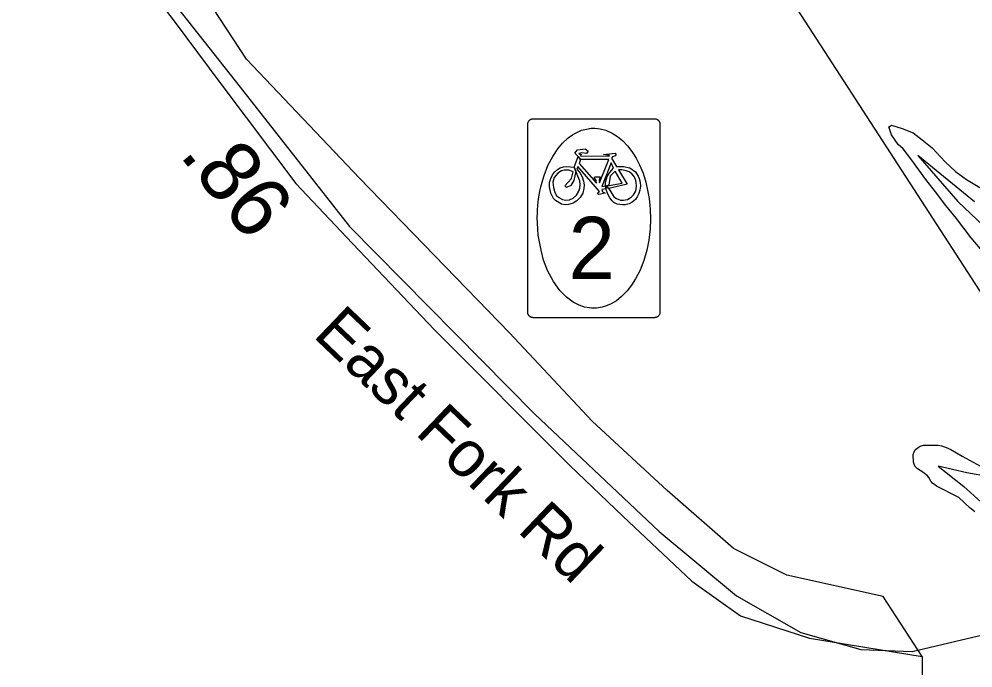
# Model space of a CAD drawing. Extents: x 1662474 to 1856135, y 779280 to 917889.
# Drawn here: x 1719329 to 1721283, y 823551 to 824881 of the extents above; entities that cross this region are included whole.
import ezdxf

# ---------------------------------------------------------------- set-up
doc = ezdxf.new("R2010")
doc.units = 0
for name, color, linetype in [('Exist Boundary Political City Limit New', 7, 'Continuous'), ('Exist Boundary Political City Limit New Hole', 7, 'Continuous'), ('Exist Hydrographic Lake Shore', 7, 'Continuous'), ('Exist Road Primary NC Shield Bike CELL', 7, 'Continuous'), ('Exist Road Primary NC Shield Bike NC Label', 7, 'Continuous'), ('Exist Road Secondary Mileage Tenths English Label', 7, 'Continuous'), ('Exist Road Secondary Structure Standard Bridge Number Label', 7, 'Continuous'), ('Exist Road Secondary Type 51 Attributed', 7, 'Continuous'), ('Exist Road Secondary Type 51 Label', 7, 'Continuous'), ('Map Preparation Boundary City Limit Buffer Line', 7, 'Continuous'), ('Old_Level_44', 7, 'Continuous')]:
    doc.layers.add(name, color=color, linetype=linetype)

msp = doc.modelspace()

# ---------------------------------------------------------------- linework, layer by layer
at = {"layer": 'Exist Boundary Political City Limit New'}
for points in [[(1719315.9, 825244.6), (1719397.1, 825175.9), (1719546.9, 825009.6), (1719554, 825000), (1719602.4, 824935.2), (1719646.4, 824876.2), (1719742.4, 824747.6), (1719896.1, 824543.8), (1720000, 824433.9), (1720179, 824244.4), (1720457.6, 823965.8), (1720565.8, 823861.8), (1720707.1, 823728.7), (1720806.9, 823658), (1720948.4, 823612.2), (1721179.4, 823574.5)], [(1721179.4, 823574.5), (1721179.4, 823520.1)]]:
    msp.add_lwpolyline(points, dxfattribs=at)
at = {"layer": 'Exist Boundary Political City Limit New Hole'}
for points in [[(1721179.4, 823574.5), (1721099.2, 823697.6), (1720902.1, 823741.4), (1720792.6, 823796.1), (1720656.5, 823914.4), (1720503.1, 824056.8), (1720333.4, 824237.4), (1720026.6, 824554.9), (1719795, 824798.7), (1719645.5, 825027.3), (1719572.1, 825148.3), (1719468, 825252.3), (1719304.1, 825346.5)], [(1719315.9, 825244.6), (1719397.1, 825175.9), (1719546.9, 825009.6), (1719554, 825000), (1719602.4, 824935.2), (1719646.4, 824876.2), (1719742.4, 824747.6), (1719896.1, 824543.8), (1720000, 824433.9), (1720179, 824244.4), (1720457.6, 823965.8), (1720565.8, 823861.8), (1720707.1, 823728.7), (1720806.9, 823658), (1720948.4, 823612.2), (1721179.4, 823574.5)]]:
    msp.add_lwpolyline(points, dxfattribs=at)
at = {"layer": 'Exist Hydrographic Lake Shore'}
for points in [[(1721298.5, 824409.5), (1721279.4, 824432.3), (1721249.5, 824472.2), (1721227.4, 824498.7), (1721206.6, 824526.8), (1721186.8, 824552), (1721158.1, 824591.6), (1721140, 824614.4), (1721130.2, 824623.9), (1721116.4, 824643.1), (1721111.1, 824659.9), (1721114, 824661.7), (1721116.4, 824663), (1721138.4, 824656.4), (1721160.5, 824647.2), (1721179.4, 824633.1), (1721199.6, 824616.6), (1721226.1, 824588.2), (1721247.4, 824568.5), (1721269.9, 824551.8), (1721297.2, 824535.8)], [(1721286.8, 823870.9), (1721277, 823879.1), (1721254.4, 823900.6), (1721208.5, 823923.7), (1721204.9, 823926), (1721200.6, 823929.4), (1721197.2, 823933.6), (1721193, 823941.5), (1721190.1, 823944.9), (1721180.6, 823952), (1721169.6, 823959.1), (1721164.4, 823964.6), (1721162.6, 823968.8), (1721161.5, 823973), (1721161, 823988.2), (1721162.9, 823994.2), (1721165.8, 823998.4), (1721171, 824002.9), (1721174.9, 824005.3), (1721182, 824007.4), (1721212.1, 824007.9), (1721219, 824006.3), (1721226.9, 824003.7), (1721237.6, 823999), (1721260.8, 823985.3), (1721306.4, 823960.7)]]:
    msp.add_lwpolyline(points, dxfattribs=at)
at = {"layer": 'Exist Road Primary NC Shield Bike CELL'}
for points in [[(1720381, 824676.2), (1720381.8, 824676.3), (1720414.8, 824676.3), (1720598.2, 824676.3), (1720631.2, 824676.3), (1720632.4, 824676.2), (1720633, 824676.1), (1720633.8, 824675.9), (1720634.5, 824675.7), (1720635.2, 824675.5), (1720636.5, 824674.8), (1720637.2, 824674.4), (1720637.8, 824674), (1720638.5, 824673.3), (1720639.4, 824672.3), (1720640.1, 824671.5), (1720640.3, 824671.1), (1720640.5, 824670.7), (1720640.8, 824670.2), (1720641, 824669.8), (1720641.2, 824669.3), (1720641.5, 824668.6), (1720641.7, 824667.6), (1720641.8, 824666.8), (1720641.9, 824666.4), (1720641.9, 824666), (1720641.9, 824632.5), (1720641.9, 824312.7), (1720641.9, 824279.6), (1720641.8, 824278.4), (1720641.7, 824277.8), (1720641.6, 824277), (1720641.4, 824276.3), (1720641.1, 824275.6), (1720640.4, 824274.2), (1720640.1, 824273.6), (1720639.6, 824273), (1720639, 824272.3), (1720638.5, 824271.9), (1720638, 824271.3), (1720637.7, 824271.1), (1720637.2, 824270.7), (1720636.8, 824270.4), (1720636.4, 824270.2), (1720635.9, 824270), (1720635, 824269.6), (1720634.2, 824269.3), (1720633.3, 824269.1), (1720632.9, 824269), (1720632.4, 824268.9), (1720632.1, 824268.9), (1720631.7, 824268.9), (1720631.1, 824268.8), (1720598.1, 824268.8), (1720414.8, 824268.8), (1720381.8, 824268.8), (1720381.2, 824268.9), (1720380.6, 824268.9), (1720380, 824269), (1720379.2, 824269.2), (1720378.5, 824269.4), (1720377.8, 824269.7), (1720377.1, 824270), (1720376.5, 824270.3), (1720375.9, 824270.7), (1720375.2, 824271.1), (1720374.9, 824271.4), (1720374.5, 824271.8), (1720374.3, 824272), (1720373.9, 824272.5), (1720373.5, 824272.9), (1720373.1, 824273.4), (1720372.8, 824273.8), (1720372.6, 824274.2), (1720372.3, 824274.8), (1720372, 824275.3), (1720371.8, 824275.8), (1720371.7, 824276.1), (1720371.6, 824276.4), (1720371.5, 824276.7), (1720371.5, 824276.9), (1720371.4, 824277.1), (1720371.3, 824277.3), (1720371.3, 824277.6), (1720371.2, 824277.8), (1720371.2, 824278.1), (1720371.2, 824278.3), (1720371.2, 824278.5), (1720371.1, 824278.8), (1720371.1, 824279.4), (1720371.1, 824312.6), (1720371.1, 824632.5), (1720371.1, 824665.6), (1720371.2, 824666.7), (1720371.3, 824667.4), (1720371.4, 824668.1), (1720371.6, 824668.9), (1720371.9, 824669.6), (1720372.6, 824670.9), (1720373, 824671.5), (1720373.4, 824672.1), (1720374, 824672.8), (1720375, 824673.8), (1720375.8, 824674.4), (1720376.3, 824674.7), (1720376.6, 824674.9), (1720377.1, 824675.2), (1720377.6, 824675.3), (1720378, 824675.6), (1720378.8, 824675.8), (1720379.7, 824676), (1720380.6, 824676.2)], [(1720506.5, 824288.3), (1720501.8, 824288.5), (1720497.4, 824288.9), (1720487.5, 824290.6), (1720476.2, 824294.7), (1720469.7, 824297.9), (1720464.4, 824300.9), (1720458.7, 824304.8), (1720450.7, 824310.7), (1720437, 824324.6), (1720423.5, 824342.6), (1720411.7, 824365.7), (1720403.4, 824386.6), (1720398.2, 824407), (1720392.5, 824437.9), (1720390.7, 824462.3), (1720390.6, 824474.2), (1720390.7, 824482.8), (1720391, 824489), (1720391.7, 824498.3), (1720393.1, 824512.6), (1720395.8, 824527.3), (1720397.8, 824536.7), (1720399.1, 824541.9), (1720401.8, 824551.5), (1720404.4, 824560), (1720412.3, 824580.5), (1720422.1, 824599.1), (1720432.9, 824614.7), (1720442.4, 824626.4), (1720453.9, 824637.2), (1720462.8, 824643.2), (1720467.4, 824645.9), (1720472.7, 824648.7), (1720481.3, 824652.7), (1720491.6, 824655.3), (1720501, 824656.8), (1720508.7, 824657), (1720519.5, 824655.8), (1720530.9, 824652.8), (1720543.9, 824647.1), (1720555.2, 824640.2), (1720564.9, 824631.9), (1720575.6, 824620.9), (1720584.3, 824609.5), (1720592.9, 824595.6), (1720600, 824582), (1720607.2, 824564.8), (1720612.7, 824546.7), (1720616.7, 824529.7), (1720619.7, 824513.1), (1720621.2, 824498.5), (1720621.8, 824490.4), (1720622.7, 824471.4), (1720621.8, 824451.1), (1720619.1, 824427.5), (1720614.8, 824406.8), (1720609, 824385.9), (1720601.2, 824365.8), (1720592.1, 824348.2), (1720583.5, 824335.1), (1720574.7, 824323.6), (1720563.4, 824311.9), (1720553.1, 824303.6), (1720541.9, 824297.1), (1720530.4, 824292.2), (1720523.3, 824290.3), (1720519.2, 824289.6), (1720515.7, 824288.9), (1720511.9, 824288.6)], [(1720526, 824603), (1720550.1, 824605.9), (1720551.9, 824604.1), (1720550.4, 824600.3), (1720544.5, 824598.5), (1720542.9, 824595.3), (1720553, 824578.2), (1720567.5, 824578.8), (1720580.4, 824576), (1720591.6, 824567.4), (1720597, 824558.8), (1720599.5, 824554.2), (1720601.4, 824546.4), (1720601.8, 824538.2), (1720600.7, 824529.7), (1720598.9, 824523.2), (1720595.3, 824516.3), (1720591.8, 824511.2), (1720585, 824505.7), (1720578.9, 824502.2), (1720570.5, 824500.1), (1720565.2, 824499.8), (1720554.5, 824501.5), (1720547.6, 824505), (1720544.2, 824507.9), (1720539, 824514.3), (1720535.7, 824520.4), (1720531, 824532.6), (1720530, 824538.5), (1720537.4, 824533.2), (1720543.2, 824523.3), (1720547.3, 824516.6), (1720552.6, 824512.8), (1720560.8, 824509.5), (1720566.9, 824509.3), (1720575.1, 824511.2), (1720582.6, 824515.4), (1720588, 824520.8), (1720592.3, 824527.9), (1720593.7, 824537.9), (1720593.5, 824546.1), (1720591.6, 824552.8), (1720588.1, 824558.9), (1720584.5, 824563.2), (1720578.6, 824567.7), (1720572.9, 824569.5), (1720563.5, 824571.4), (1720557, 824572), (1720574.5, 824542.5), (1720537.4, 824533.2), (1720530, 824538.5), (1720564.2, 824544.7), (1720549.9, 824569.1), (1720540.1, 824558.5), (1720537.2, 824540), (1720530, 824538.5), (1720530.4, 824546.3), (1720533.5, 824558.1), (1720538.9, 824566.3), (1720546.7, 824575.2), (1720541.8, 824585.7), (1720523, 824537.8), (1720530.1, 824538.6), (1720531, 824532.6), (1720522.6, 824531.6), (1720524.4, 824526.5), (1720529.4, 824523.7), (1720516.9, 824520.9), (1720513.8, 824524.8), (1720518.3, 824527.2), (1720473.6, 824578.3), (1720471.9, 824573.4), (1720478.1, 824565.1), (1720482.3, 824557.1), (1720485, 824548.5), (1720486.4, 824541.1), (1720485.7, 824533.6), (1720483.6, 824523.7), (1720478.7, 824514.8), (1720471.8, 824508.1), (1720464, 824503.3), (1720454.4, 824500.9), (1720447.4, 824500.3), (1720440.3, 824501.2), (1720428, 824508.8), (1720424, 824513.3), (1720418.3, 824523.7), (1720415.8, 824536.6), (1720415.7, 824545.8), (1720418, 824554), (1720421.6, 824561.3), (1720425.8, 824566.6), (1720431.9, 824572.6), (1720437.2, 824576), (1720444.1, 824578), (1720451.1, 824578.7), (1720466.3, 824577), (1720469.8, 824568.8), (1720465.2, 824549.8), (1720459.1, 824539.9), (1720450.3, 824535.7), (1720446.8, 824539.2), (1720461, 824553.7), (1720464.1, 824567.5), (1720460.9, 824568.9), (1720454.9, 824570.8), (1720445.4, 824571.1), (1720439.9, 824569.4), (1720432.5, 824565.1), (1720425.4, 824555.8), (1720422.3, 824546.1), (1720423.6, 824535.5), (1720426.3, 824525.5), (1720429.8, 824519.1), (1720434.9, 824515.1), (1720442.1, 824510.6), (1720448.6, 824509.5), (1720456.6, 824510), (1720464.4, 824513.4), (1720471.1, 824520.1), (1720475.4, 824528.3), (1720477.9, 824534), (1720478.5, 824541.4), (1720477.5, 824549.3), (1720473.7, 824558.4), (1720466.3, 824577), (1720474, 824598.8), (1720479.4, 824593.1), (1720476.5, 824584.5), (1720512.1, 824544.7), (1720511, 824549.7), (1720507.3, 824556.1), (1720509, 824557.5), (1720519.2, 824557.5), (1720517.3, 824550.2), (1720518.3, 824545), (1720537.2, 824592.7), (1720479.4, 824593.1), (1720474, 824598.8), (1720467.4, 824605.8), (1720473.1, 824612.6), (1720488.4, 824614.5), (1720494.5, 824609.7), (1720491.2, 824605.4), (1720481.9, 824606.5), (1720475.5, 824605), (1720477, 824603.7), (1720480.2, 824603.7), (1720478.8, 824600.5), (1720538, 824600), (1720538.4, 824601.4)]]:
    msp.add_lwpolyline(points, close=True, dxfattribs=at)
at = {"layer": 'Exist Road Secondary Structure Standard Bridge Number Label'}
msp.add_line((1721599, 823856.7), (1720324.2, 825828.1), dxfattribs=at)
at = {"layer": 'Exist Road Secondary Type 51 Attributed'}
msp.add_lwpolyline([(1719307.1, 825280.6), (1719364.3, 825236.7), (1719434.6, 825179.6), (1719491.7, 825109.3), (1719781.8, 824741.3), (1720005.9, 824455.8), (1720385.2, 824072), (1720640.2, 823830.4), (1720798.4, 823698.6), (1720930.2, 823624), (1721053.3, 823588.9), (1721158.8, 823584.5), (1721381.2, 823637.2), (1721574.5, 823725), (1721642.4, 823764.4)], dxfattribs=at)
at = {"layer": 'Map Preparation Boundary City Limit Buffer Line'}
for points in [[(1721179.4, 823574.5), (1721099.2, 823697.6), (1720902.1, 823741.4), (1720792.6, 823796.1), (1720656.5, 823914.4), (1720503.1, 824056.8), (1720333.4, 824237.4), (1720026.6, 824554.9), (1719795, 824798.7), (1719645.5, 825027.3), (1719572.1, 825148.3), (1719468, 825252.3), (1719304.1, 825346.5)], [(1719315.9, 825244.6), (1719397.1, 825175.9), (1719546.9, 825009.6), (1719554, 825000), (1719602.4, 824935.2), (1719646.4, 824876.2), (1719742.4, 824747.6), (1719896.1, 824543.8), (1720000, 824433.9), (1720179, 824244.4), (1720457.6, 823965.8), (1720565.8, 823861.8), (1720707.1, 823728.7), (1720806.9, 823658), (1720948.4, 823612.2), (1721179.4, 823574.5)], [(1719315.9, 825244.6), (1719397.1, 825175.9), (1719546.9, 825009.6), (1719554, 825000), (1719602.4, 824935.2), (1719646.4, 824876.2), (1719742.4, 824747.6), (1719896.1, 824543.8), (1720000, 824433.9), (1720179, 824244.4), (1720457.6, 823965.8), (1720565.8, 823861.8), (1720707.1, 823728.7), (1720806.9, 823658), (1720948.4, 823612.2), (1721179.4, 823574.5)], [(1721179.4, 823574.5), (1721179.4, 823520.1)]]:
    msp.add_lwpolyline(points, dxfattribs=at)
at = {"layer": 'Old_Level_44'}
for points in [[(1721286.5, 824506.4), (1721170, 824600.8), (1721252.2, 824506.5), (1721343.9, 824420.4)], [(1721362.3, 823934.3), (1721270.8, 823950.6), (1721211.7, 823964.7), (1721264.6, 823923), (1721333.9, 823860)]]:
    msp.add_lwpolyline(points, dxfattribs=at)

# ---------------------------------------------------------------- texts
at = {"layer": 'Exist Road Primary NC Shield Bike NC Label'}
msp.add_text('2', height=127.5, dxfattribs=at).set_placement((1720454.8, 824347.9))
at = {"layer": 'Exist Road Secondary Mileage Tenths English Label'}
msp.add_text('.86', height=125, rotation=308.8404, dxfattribs=at).set_placement((1719655.4, 824602.3))
at = {"layer": 'Exist Road Secondary Type 51 Label'}
msp.add_text('East Fork Rd', height=95, rotation=316.327, dxfattribs=at).set_placement((1719928.8, 824231.3))

doc.saveas('drawing.dxf')
